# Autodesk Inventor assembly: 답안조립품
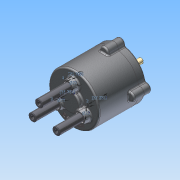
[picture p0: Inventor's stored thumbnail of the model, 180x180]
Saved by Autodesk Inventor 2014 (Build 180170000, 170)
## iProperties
Created: 2015-09
Part Number: 답안조립품
Document SubType Name: Assembly
Designer: study
Author: study
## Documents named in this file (14)
- C:\Users\study\Desktop\350916V1004\답안조립품.iam
- C:\Users\study\Desktop\350916V1004\몸체.ipt
- C:\Users\study\Desktop\350916V1004\멈춤링 10 x 1.ipt
- C:\Users\study\Desktop\350916V1004\멈춤링 22 x 1.2.ipt
- C:\Users\study\Desktop\350916V1004\메인 축.ipt
- C:\Users\study\Desktop\350916V1004\베어링 NA 4900.ipt
- C:\Users\study\Desktop\350916V1004\슬라이드 축.ipt
- C:\Users\study\Desktop\350916V1004\판캠.ipt
- C:\Users\study\Desktop\350916V1004\M5x0.8x20.ipt
- C:\Users\study\Desktop\350916V1004\오일실.ipt
- C:\Users\study\Desktop\350916V1004\커버.ipt
- C:\Users\study\Desktop\350916V1004\11-가변스프링.ipt
- C:\Users\study\Desktop\350916V1004\12-가변스프링.ipt
- C:\Users\study\Desktop\350916V1004\13-가변스프링.ipt
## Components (7 placed, 4 different names)
1. 11-가변스프링:1
2. 12-가변스프링:1
3. 13-가변스프링:1
4. M5x0.8x20:1
5. M5x0.8x20:2
6. M5x0.8x20:3
7. M5x0.8x20:4
